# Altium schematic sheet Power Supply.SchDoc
size A
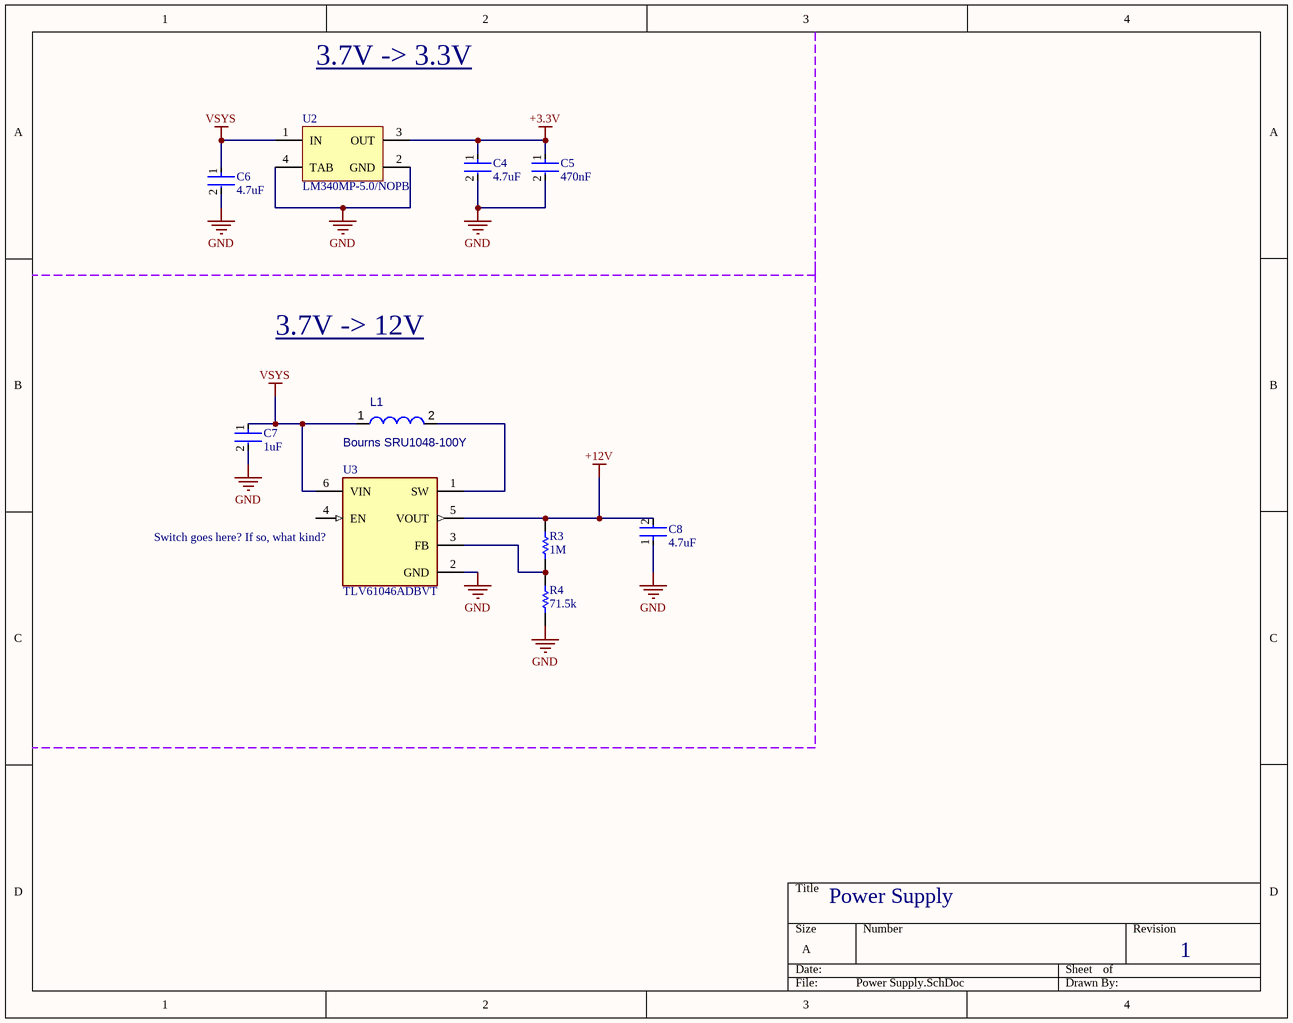
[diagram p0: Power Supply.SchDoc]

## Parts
C4  4.7uF  [FP-CC0805-0_85-MFG]
C5  470nF  [FP-CC0805-0_85-MFG]
C6  4.7uF  [FP-CC0805-0_85-MFG]
C7  1uF  [FP-CC0805-0_85-MFG]
C8  4.7uF  [FP-CC0805-0_85-MFG]
L1  Bourns SRU1048-100Y  [Bourns SRU1048-100Y-Footprint-1]
R3  value 1M  [RESC2013X70X40ML20T20]  (hidden comment: Resistor 1k +/-1% 0805 125 mW)
R4  value 71.5k  [RESC2013X70X40ML20T20]  (hidden comment: Resistor 1k +/-1% 0805 125 mW)
U2  LM340MP-5.0/NOPB  [DCY0004A_L]
U3  TLV61046ADBVT  [FP-DBV0006A-MFG]

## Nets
+3.3V: C4.1 C5.1 U2.3(OUT)
+12V: C8.2 R3.2 U3.5(VOUT)
GND: C4.2 C5.2 C6.2 C7.2 C8.1 R4.1 U2.2(GND) U2.4(TAB) U3.2(GND)
VSYS: C6.1 C7.1 L1.1 U2.1(IN) U3.6(VIN)
NetL1_2: L1.2 U3.1(SW)
NetR3_1: R3.1 R4.2 U3.3(FB)

Not connected (* = marked no-connect by the designer): U3 4(EN)

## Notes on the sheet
- 3.7V -> 3.3V
- 3.7V -> 12V
- (near U3) Switch goes here? If so, what kind?
- Power Supply
- 1

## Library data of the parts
C4-C8 = CMP-03422-000499-1: CAP CER 0.1UF 50V X7R 0805; Manufacturer Part Number: CC0805KRX7R9BB104; Manufacturer: Yageo; Tolerance: 0.1; Capacitance: 100 nF; Value: 100 nF; Material: Ceramic
L1 = CMP-006-00021-1: Inductor
R3 R4 = CMP-009-00010-4: Chip Resistor, 1 KOhm, +/- 1%, 0.125 W, -55 to 155 degC, 0805 (2013 Metric); Power: 125mW; Voltage Rating: 150V
U2 = CMP-0062-01784-3: Series 3-Terminal Positive Regulators, 4-pin SOT-223, Pb-Free; Manufacturer: Texas Instruments; PowerWise: N; CompType: LDO IC; PackageTopMarking: XYTT*N00A
U3 = CMP-04918-000055-1: IC REG BOOST ADJ SOT23-6; Manufacturer: Texas Instruments; Output Current: 980mA; Standoff Height: 0mm; Output Type: AdjustableProgrammable; Switching Frequency: 1050kHz; Max Junction Temp: +125°C; Nominal Supply Current: 110uA; Number Of Outputs: 1; Output Voltage: 3.3-28V; Min Supply Voltage: 1.8V; Max Duty Cycle: 90%; Max Supply Voltage: 5.5V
